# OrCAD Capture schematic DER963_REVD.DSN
size C; title: DER 668 - 5V 1.5A; rev: B
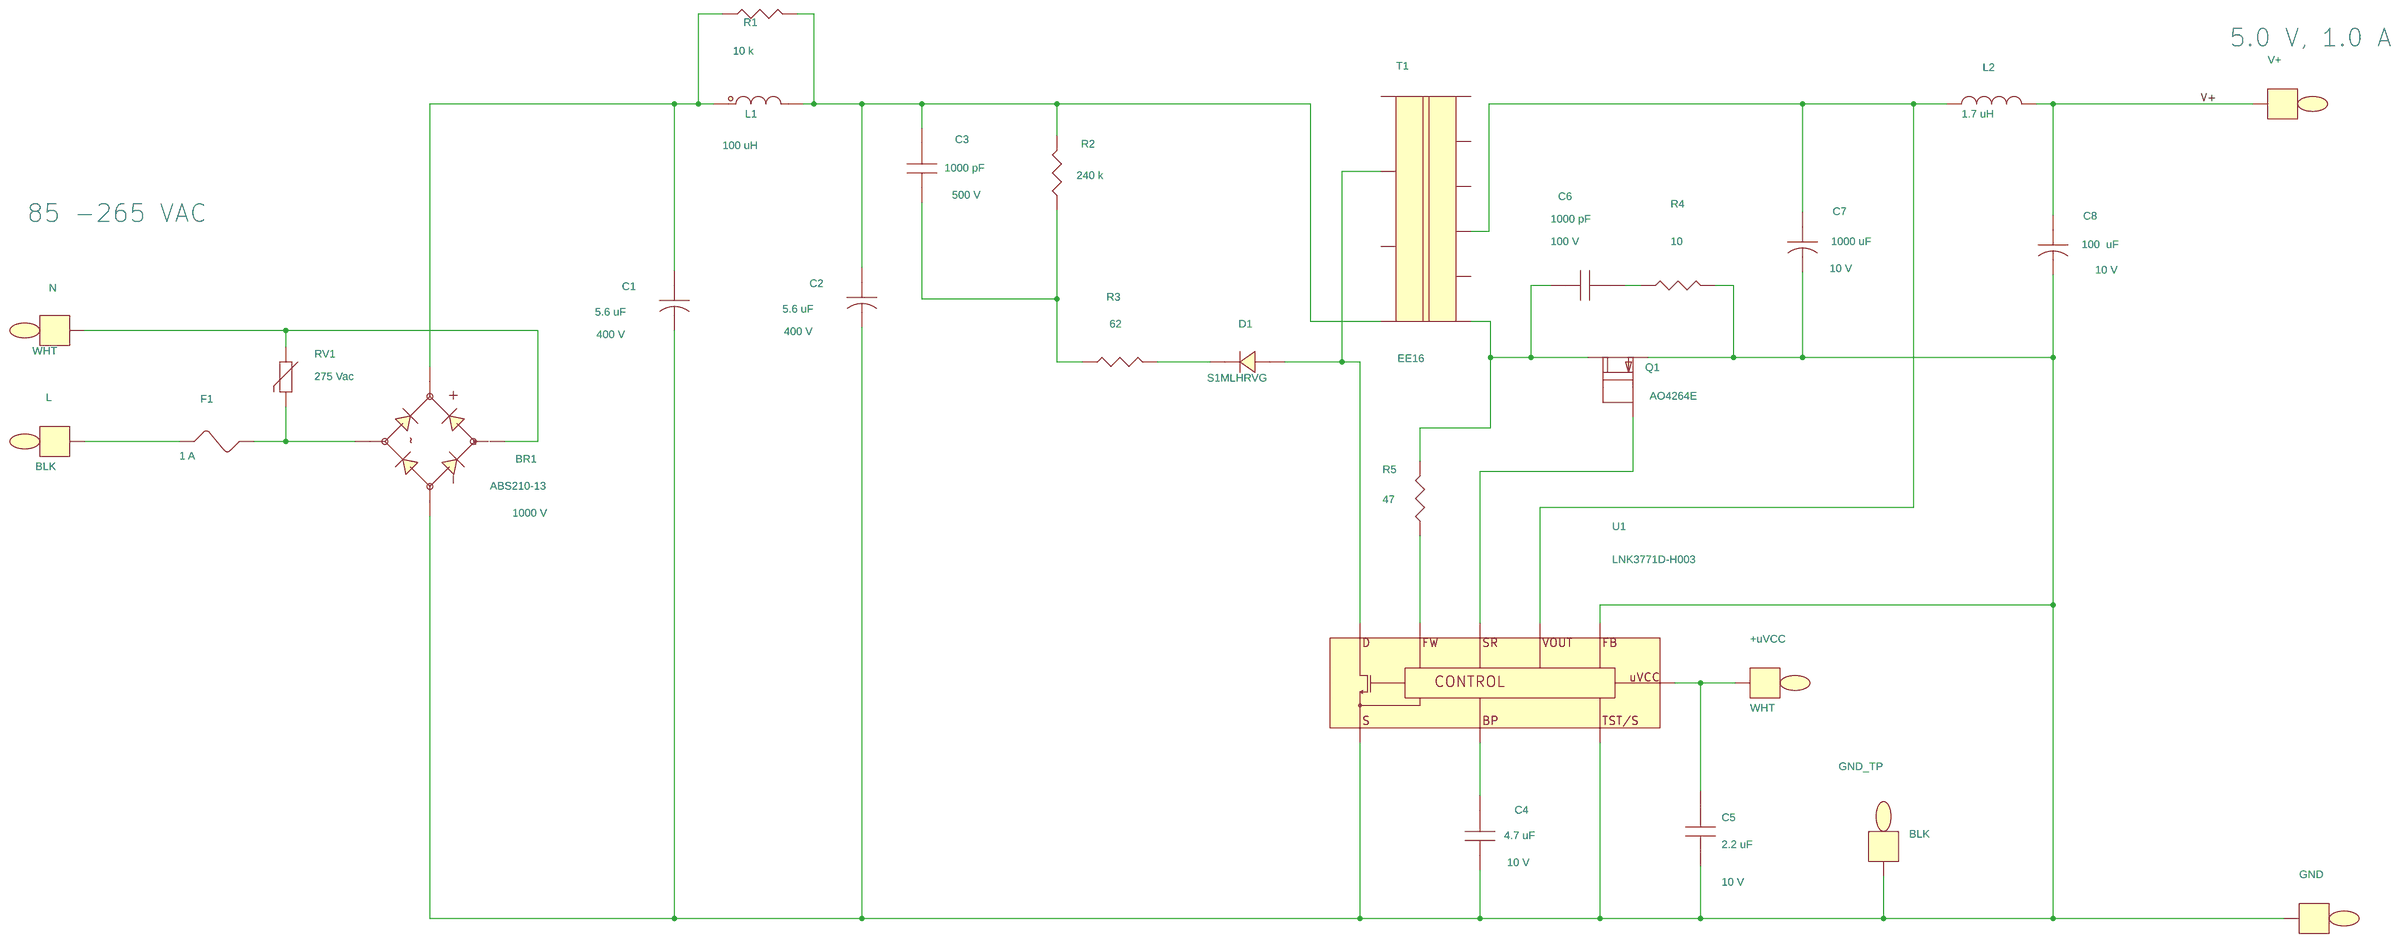
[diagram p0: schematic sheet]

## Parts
+uVCC  WHT  [pitpkeystone100x100]
BR1  ABS210-13  [pismd_SOPA-4]
C1  5.6 uF  [pipolcapcyld315ls138d030]
C2  5.6 uF  [pipolcapcyld315ls138d030]
C3  1000 pF  [pismc0805]
C4  4.7 uF  [pismc0805]
C5  2.2 uF  [pismc0805]
C6  1000 pF  [pismc0603]
C7  1000 uF  [pipolcapcyld400ls200040]
C8  100  uF  [pipolcapclyd200ls80030]
D1  S1MLHRVG  [pi_sm_sod-123_12]
F1  1 A  [pi_rst_microfuse]
GND  GND  [pitpkeystone100x100]
GND_TP  BLK  [pitpkeystone100x100]
L  BLK  [pitpkeystone100x100]
L1  100 uH  [pi_choke_RL5480-2_d2]
L2  1.7 uH  [pichoke6mm2pin4mmLSd030]
N  WHT  [pitpkeystone100x100]
Q1  AO4264E  [pismso8]
R1  10 k  [pismr1206]
R2  240 k  [pismr0805]
R3  62  [pismr0805]
R4  10  [pismr0805]
R5  47  [pismr1206]
RV1  275 Vac  [pidisc500x225ls335x140040]
T1  EE16  [pibobbinee1610p4x6]
U1  LNK3771D-H003  [pi_smd_so_14-16p_short9-14]
V+  RED  [pitpkeystone100x100]

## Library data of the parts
+uVCC N = TESTPOINT: Part Number: 35-00081-00
BR1 = DIODE_BRIDGE_+~~-: ALT_SYMBOLS: pismd_SOPA-4a,pi_sm_soic4_slot; Disp_Voltage: 1000 V; FPLIST: pismd_SOPA-4,pismd_SOPA-4a,pi_sm_soic4_slot; Part Number: 15-01254-00
C1 C2 = CAP_POL: ALT_SYMBOLS: pipolcapcyld315ls138d030h; Disp_Voltage: 400 V; FPLIST: pipolcapcyld315ls138d030,pipolcapcyld315ls138d030h; Part Number: 20-08972-00; Voltage: 400 V
C3 = CAP_NP: Disp_Voltage: 500 V; Part Number: 20-09036-00; Voltage: 500 V
C4 = CAP_NP: Disp_Voltage: 10 V; Part Number: 20-01487-00; Voltage: 10 V
C5 = CAP_NP: Disp_Voltage: 10 V; Part Number: 20-08747-00; Voltage: 10 V
C6 = CAP_NP: Disp_Voltage: 100 V; Part Number: 20-00712-00; Voltage: 100 V
C7 = CAP_POL: ALT_SYMBOLS: pipolcapclyd395x630ls200030h; Disp_Voltage: 10 V; FPLIST: pipolcapcyld400ls200040,pipolcapclyd395x630ls200030h; Part Number: 20-00007-00; Voltage: 10 V
C8 = CAP_POL: ALT_SYMBOLS: pipolcapclyd200ls80030h; Disp_Voltage: 10 V; FPLIST: pipolcapclyd200ls80030,pipolcapclyd200ls80030h; Part Number: 20-00001-00; Voltage: 10 V
D1 = DIODE: Disp_Voltage: 1 kV; Part Number: 15-01663-00
F1 = FUSE: ALT_SYMBOLS: pirstmicrofusehoz; FPLIST: pi_rst_microfuse,pirstmicrofusehoz; Part Number: 40-00053-00
GND = TESTPOINT: Part Number: 35-00079-00
GND_TP L = TESTPOINT: ALT_SYMBOLS: TP_TH_CR2_D1_1; FPLIST: pitpkeystone100x100,TP_TH_CR2_D1_1; Part Number: 35-00079-00
L1 = INDUCTOR_dot2: ALT_SYMBOLS: pi_choke_RL5480-2H_d2; FPLIST: pi_choke_RL5480-2_d2,pi_choke_RL5480-2H_d2; Part Number: 30-00306-00
L2 = INDUCTOR: Part Number: 30-00451-00
Q1 = FET_P_SGD_123_4_5678: Part Number: 50-00368-00
R1 = R: Part Number: 05-01376-00
R2 = R: Part Number: 05-01576-00
R3 = R: ALT_SYMBOLS: Unisem_RMCF0805UL; FPLIST: pismr0805,Unisem_RMCF0805UL; Part Number: 05-01490-00
R4 = R: Disp_Tol: 1%; Part Number: 05-00492-00
R5 = R: Part Number: 05-01320-00
RV1 = VARISTOR: Part Number: 85-00027-00
T1 = BEE16_10P_4x6_GENERIC: Part Number: 25-00846-00
U1 = LNKXT2-SR2aL: Part Number: 10-01359-01
V+ = TESTPOINT: Part Number: 35-00080-00

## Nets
V+: C8.1 L2.2 V+.1
N2618494: BR1.1 C1.1 L1.2 R1.1
N2618510: C2.1 C3.2 L1.1 R1.2 R2.2 T1.4
N2618826: C3.1 R2.1 R3.1
N2618854: C6.2 R4.2
N2618858: BR1.4 C1.2 C2.2 C4.1 C5.1 C7.2 C8.2 GND.1 GND_TP.1 Q1.1(S) R4.1 U1.1 U1.5 U1.9
N2618994: D1.1 R3.2
N2618998: D1.2 T1.2 U1.8
N2619088: Q1.4(G) U1.3
N2626861: BR1.2 N.1 RV1.1
N11228917: BR1.3 F1.2 RV1.2
N11238573: C7.1 L2.1 T1.7 U1.2
N11247136: C6.1 Q1.5(D) R5.1 T1.5
N11280302: F1.1 L.1
N11283147: R5.2 U1.4
N11283765: C4.2 U1.16
N11284197: +uVCC.1 C5.2 U1.15

Not connected (* = marked no-connect by the designer): Q1 2(S2) 3(S3) 6(D6) 7(D7) 8(D8); T1 1 3 6 8 9 10; U1 10 11 12 13 14

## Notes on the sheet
- 5.0 V, 1.0 A
- 85 -265 VAC
